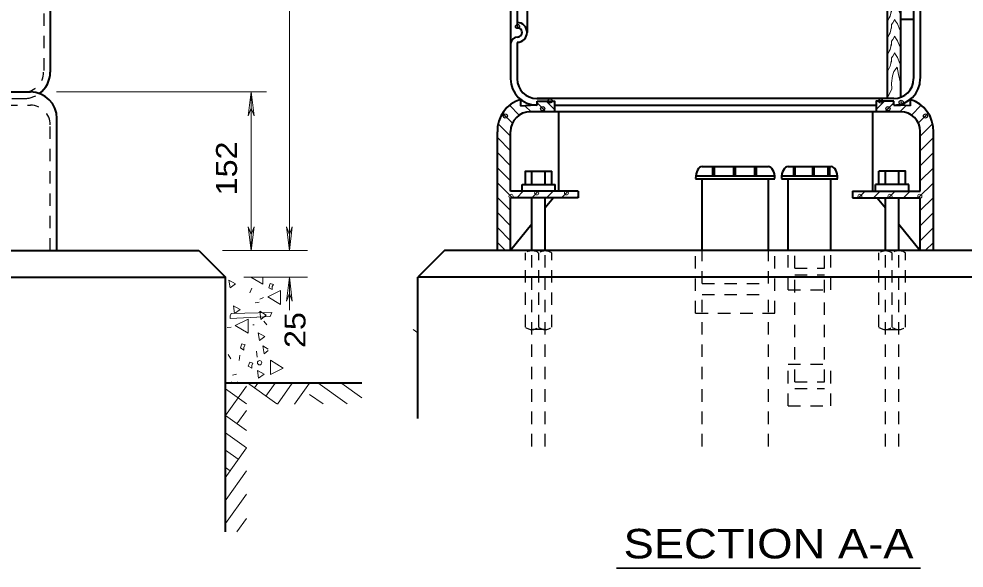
# Model space of a CAD drawing. Extents: x 312583 to 312854, y 144419 to 144597.
# Drawn here: x 312696.89 to 312731.16, y 144509.33 to 144529.22 of the extents above; entities that cross this region are included whole.
import ezdxf
from ezdxf.enums import TextEntityAlignment as Align

# ---------------------------------------------------------------- set-up
doc = ezdxf.new("R2010")
doc.units = 0
doc.header["$LTSCALE"] = 0.3
doc.header["$PDMODE"] = 32
doc.header["$PDSIZE"] = 0.15
doc.linetypes.add('SHORT_DASHED', pattern=[2.7, 1.5, -1.2])
doc.layers.add('1', color=7, linetype='Continuous', lineweight=25)
doc.layers.add('2', color=7, linetype='Continuous', lineweight=13)

msp = doc.modelspace()

# ---------------------------------------------------------------- linework, layer by layer
at = {"layer": '1', "lineweight": 40}
for p, q in [((312728.3725, 144566.588), (312728.3725, 144526.338)), ((312728.8555, 144566.542), (312728.8555, 144526.3763)), ((312698.0298, 144565.8673), (312698.0298, 144527.2963)), ((312729.3309, 144565.8673), (312729.3309, 144527.0586)), ((312729.5685, 144565.8673), (312729.5685, 144527.0586)), ((312715.3162, 144564.7863), (312715.3162, 144528.73)), ((312714.9559, 144564.6253), (312714.9559, 144528.8986)), ((312728.8555, 144529.213), (312729.3309, 144529.213)), ((312714.9559, 144528.3696), (312714.9559, 144527.0586)), ((312670.4758, 144526.5756), (312697.3091, 144526.5756)), ((312715.0785, 144526.3073), (312715.0785, 144526.0696)), ((312715.0785, 144526.0696), (312715.4389, 144526.1003)), ((312715.6765, 144526.1003), (312715.4389, 144526.1003)), ((312716.0982, 144526.338), (312715.6765, 144526.338)), ((312715.6765, 144526.338), (312716.0982, 144526.338)), ((312715.6765, 144526.1003), (312715.6765, 144526.246)), ((312715.6765, 144526.2076), (312715.6765, 144526.2306)), ((312728.6102, 144526.338), (312716.0982, 144526.338)), ((312716.3129, 144526.1003), (312716.3129, 144525.855)), ((312716.3129, 144526.1003), (312727.9739, 144526.1003)), ((312727.9739, 144526.1003), (312727.9739, 144525.855)), ((312728.6102, 144526.338), (312728.1962, 144526.338)), ((312728.6102, 144526.1003), (312728.6102, 144526.246)), ((312728.6102, 144526.2076), (312728.6102, 144526.2306)), ((312728.6102, 144526.1003), (312728.8555, 144526.1003)), ((312729.2082, 144526.0696), (312728.8555, 144526.1003)), ((312729.2082, 144526.3073), (312729.2082, 144526.0696)), ((312728.8555, 144525.855), (312715.4389, 144525.855)), ((312716.4509, 144525.855), (312716.4509, 144522.98)), ((312727.8359, 144525.855), (312727.8359, 144522.98)), ((312698.2675, 144520.8256), (312698.2675, 144525.6173)), ((312714.2429, 144520.818), (312714.2429, 144525.1343)), ((312714.7182, 144522.98), (312714.7182, 144525.142)), ((312729.5685, 144522.98), (312729.5685, 144525.142)), ((312730.0515, 144520.818), (312730.0515, 144525.1343)), ((312715.4925, 144523.2253), (312715.4925, 144523.7006)), ((312715.9755, 144523.2253), (312715.9755, 144523.7006)), ((312716.2132, 144523.2253), (312716.2132, 144523.7006)), ((312721.6642, 144523.8693), (312724.0639, 144523.8693)), ((312722.0552, 144523.532), (312722.0552, 144523.8693)), ((312722.1089, 144523.532), (312722.1089, 144523.8693)), ((312722.8065, 144523.532), (312722.8065, 144523.8693)), ((312722.8679, 144523.532), (312722.8679, 144523.8693)), ((312723.5732, 144523.532), (312723.5732, 144523.8693)), ((312723.6345, 144523.532), (312723.6345, 144523.8693)), ((312724.7769, 144523.8693), (312726.3332, 144523.8693)), ((312724.9915, 144523.532), (312724.9915, 144523.8693)), ((312725.0375, 144523.532), (312725.0375, 144523.8693)), ((312725.6815, 144523.532), (312725.6815, 144523.8693)), ((312725.7275, 144523.532), (312725.7275, 144523.8693)), ((312726.2335, 144523.532), (312726.2335, 144523.8693)), ((312726.2949, 144523.532), (312726.2949, 144523.8693)), ((312728.0735, 144523.2253), (312728.0735, 144523.7006)), ((312728.3112, 144523.2253), (312728.3112, 144523.7006)), ((312728.7942, 144523.2253), (312728.7942, 144523.7006)), ((312721.4265, 144523.4323), (312724.3015, 144523.4323)), ((312721.4342, 144523.532), (312724.2939, 144523.532)), ((312721.6642, 144520.8256), (312721.6642, 144523.4323)), ((312724.0639, 144520.8256), (312724.0639, 144523.4323)), ((312724.5392, 144523.4323), (312726.5785, 144523.4323)), ((312724.5469, 144523.532), (312726.5709, 144523.532)), ((312724.7769, 144520.8256), (312724.7769, 144523.4323)), ((312726.3332, 144520.8256), (312726.3332, 144523.4323)), ((312717.1715, 144522.98), (312714.7182, 144522.98)), ((312715.1399, 144523.2253), (312716.3359, 144523.2253)), ((312715.1399, 144522.98), (312715.1399, 144523.2253)), ((312716.3359, 144522.98), (312716.3359, 144523.2253)), ((312717.1715, 144522.98), (312717.1715, 144522.7423)), ((312727.1152, 144522.98), (312729.5685, 144522.98)), ((312727.1152, 144522.98), (312727.1152, 144522.7423)), ((312729.1545, 144523.2253), (312727.9509, 144523.2253)), ((312727.9509, 144522.98), (312727.9509, 144523.2253)), ((312729.1545, 144522.98), (312729.1545, 144523.2253)), ((312717.1715, 144522.7423), (312714.7182, 144522.7423)), ((312714.7182, 144520.8256), (312714.7182, 144522.7423)), ((312715.4925, 144520.8256), (312715.4925, 144522.7423)), ((312716.2745, 144522.7423), (312715.9755, 144522.3743)), ((312715.9755, 144520.8256), (312715.9755, 144522.7423)), ((312727.1152, 144522.7423), (312729.5685, 144522.7423)), ((312728.0122, 144522.7423), (312728.3112, 144522.3743)), ((312728.3112, 144520.8256), (312728.3112, 144522.7423)), ((312728.7942, 144520.8256), (312728.7942, 144522.7423)), ((312729.5685, 144520.8256), (312729.5685, 144522.7423)), ((312715.4925, 144521.784), (312714.7182, 144520.8256)), ((312728.7942, 144521.784), (312729.5685, 144520.8256)), ((312630.5861, 144520.8256), (312703.4195, 144520.8256)), ((312703.4195, 144520.8256), (312704.3778, 144519.8673)), ((312712.3185, 144520.8256), (312711.3602, 144519.8673)), ((312733.4019, 144520.8256), (312712.3185, 144520.8256)), ((312629.6278, 144519.8673), (312704.3778, 144519.8673)), ((312704.3778, 144510.6366), (312704.3778, 144519.8673)), ((312734.3602, 144519.8673), (312711.3602, 144519.8673)), ((312711.3602, 144514.746), (312711.3602, 144519.8673)), ((312704.3778, 144516.034), (312709.3249, 144516.034)), ((312704.6001, 144516.034), (312709.3249, 144516.034))]:
    msp.add_line(p, q, dxfattribs=at)
at = {"layer": '1', "linetype": 'SHORT_DASHED'}
for p, q in [((312697.7921, 144565.8673), (312697.7921, 144527.2963)), ((312670.7135, 144526.5756), (312697.0715, 144526.5756)), ((312670.4758, 144526.1003), (312697.3091, 144526.1003)), ((312670.7135, 144526.338), (312697.0715, 144526.338)), ((312698.0298, 144520.8256), (312698.0298, 144525.3796)), ((312715.2549, 144518.0503), (312715.2549, 144520.7413)), ((312715.4925, 144513.734), (312715.4925, 144520.8256)), ((312715.7379, 144518.0503), (312715.7379, 144520.7413)), ((312715.9755, 144513.734), (312715.9755, 144520.8256)), ((312716.2132, 144518.0503), (312716.2132, 144520.7413)), ((312721.4265, 144518.5563), (312721.4265, 144520.8256)), ((312721.6642, 144519.6373), (312721.6642, 144520.8256)), ((312724.0639, 144519.6373), (312724.0639, 144520.8256)), ((312724.3015, 144518.5563), (312724.3015, 144520.8256)), ((312724.7769, 144519.4073), (312724.7769, 144520.8256)), ((312725.0222, 144520.1893), (312725.0222, 144520.8256)), ((312726.0955, 144520.1893), (312726.0955, 144520.8256)), ((312726.3332, 144519.4073), (312726.3332, 144520.8256)), ((312728.0735, 144518.0503), (312728.0735, 144520.7413)), ((312728.3112, 144513.734), (312728.3112, 144520.8256)), ((312728.5489, 144518.0503), (312728.5489, 144520.7413)), ((312728.7942, 144513.734), (312728.7942, 144520.8256)), ((312729.0319, 144518.0503), (312729.0319, 144520.7413)), ((312725.0222, 144520.1893), (312726.0955, 144520.1893)), ((312725.0222, 144519.944), (312726.0955, 144519.944)), ((312725.0222, 144516.0723), (312725.0222, 144519.944)), ((312726.0955, 144516.0723), (312726.0955, 144519.944)), ((312721.6642, 144519.6373), (312724.0639, 144519.6373)), ((312721.6642, 144519.2386), (312724.0639, 144519.2386)), ((312721.6642, 144513.734), (312721.6642, 144519.2386)), ((312724.0639, 144513.734), (312724.0639, 144519.2386)), ((312724.7769, 144519.4073), (312726.3332, 144519.4073)), ((312721.4265, 144518.5563), (312724.3015, 144518.5563)), ((312715.9755, 144517.9736), (312715.4925, 144517.9736)), ((312728.3112, 144517.9736), (312728.7942, 144517.9736)), ((312724.7769, 144515.206), (312724.7769, 144516.7163)), ((312724.7769, 144516.7163), (312726.3332, 144516.7163)), ((312726.3332, 144515.206), (312726.3332, 144516.7163)), ((312725.0222, 144516.0723), (312726.0955, 144516.0723)), ((312725.0222, 144515.827), (312726.0955, 144515.827)), ((312724.7769, 144515.206), (312726.3332, 144515.206))]:
    msp.add_line(p, q, dxfattribs=at)
at = {"layer": '1', "lineweight": 13}
for p, q in [((312714.6799, 144526.0926), (312715.0325, 144525.7323)), ((312715.4619, 144525.855), (312715.2395, 144526.0773)), ((312715.9985, 144525.855), (312715.6765, 144526.1846)), ((312716.3205, 144525.9316), (312715.9985, 144526.2536)), ((312727.9662, 144525.9316), (312728.2882, 144526.2536)), ((312728.2882, 144525.855), (312728.6102, 144526.1846)), ((312728.8325, 144525.855), (312729.0472, 144526.0773)), ((312729.6069, 144526.0926), (312729.2542, 144525.7323)), ((312714.8025, 144525.4333), (312714.4269, 144525.809)), ((312714.4882, 144525.74), (312714.4805, 144525.7553)), ((312729.4842, 144525.4333), (312729.8599, 144525.809)), ((312729.7985, 144525.74), (312729.8139, 144525.7553)), ((312714.7182, 144524.9733), (312714.2812, 144525.4026)), ((312729.5685, 144524.9733), (312730.0055, 144525.4026))]:
    msp.add_line(p, q, dxfattribs=at)
at = {"layer": '1', "lineweight": 40}
for points in [[(312714.7182, 144565.8673), (312714.7182, 144528.2546), (312714.7182, 144527.0586)], [(312715.6765, 144526.246), (312716.3129, 144526.246), (312716.3129, 144525.8473)], [(312728.6102, 144526.246), (312727.9739, 144526.246), (312727.9739, 144525.8473)], [(312715.2549, 144523.2253), (312715.2549, 144523.7006), (312716.2132, 144523.7006)], [(312729.0319, 144523.2253), (312729.0319, 144523.7006), (312728.0735, 144523.7006)]]:
    msp.add_lwpolyline(points, dxfattribs=at)
for centre, radius, start, end in [((312714.9664, 144528.7319), 0.1681, 266.07729, 89.01788), ((312714.9559, 144528.7319), 0.3594, 270, 90), ((312714.9993, 144528.283), 0.2846, 98.90059, 186.11318), ((312697.0705, 144527.2944), 0.9583, 306.01567, 0), ((312715.6746, 144527.0548), 0.9583, 180, 270), ((312715.6746, 144527.0548), 0.7188, 180, 270), ((312728.6121, 144527.0548), 0.9583, 270, 0), ((312728.6121, 144527.0548), 0.7188, 270, 0), ((312697.3101, 144525.6173), 0.9583, 0, 90), ((312715.4332, 144525.1659), 1.1948, 107.31785, 181.66152), ((312728.8536, 144525.1659), 1.1948, 358.33848, 72.68215), ((312715.435, 144525.1381), 0.7188, 90, 180), ((312715.435, 144525.1381), 0.7188, 90, 180), ((312728.8517, 144525.1381), 0.7188, 0, 90), ((312728.8517, 144525.1381), 0.7188, 0, 90)]:
    msp.add_arc(centre, radius, start, end, dxfattribs=at)
at = {"layer": '1', "linetype": 'SHORT_DASHED'}
for centre, radius, start, end in [((312697.0705, 144527.2944), 0.7188, 270, 0), ((312697.0705, 144527.2944), 0.9583, 270, 306.01567), ((312697.3101, 144525.3777), 0.7188, 0, 90), ((312715.4954, 144520.4379), 0.3858, 51.61151, 128.38849), ((312715.9746, 144520.4045), 0.4125, 54.49327, 125.50673), ((312728.3122, 144520.4045), 0.4125, 54.49327, 125.50673), ((312728.7913, 144520.4379), 0.3858, 51.61151, 128.38849), ((312715.4954, 144518.3823), 0.4125, 234.49327, 305.50673), ((312715.9746, 144518.3823), 0.4125, 234.49327, 305.50673), ((312728.3122, 144518.3823), 0.4125, 234.49327, 305.50673), ((312728.7913, 144518.3823), 0.4125, 234.49327, 305.50673)]:
    msp.add_arc(centre, radius, start, end, dxfattribs=at)
at = {"layer": '1', "lineweight": 40}
for centre, major_axis, start_param, end_param in [((312721.6642, 144523.4352), (0, -0.4351), 3.1415927, 4.712389), ((312724.06, 144523.4352), (0, 0.4351), 4.712389, 6.2831853), ((312724.7788, 144523.4352), (0, -0.4351), 3.1415927, 4.712389), ((312726.3361, 144523.4352), (0, 0.4351), 4.712389, 6.2831853)]:
    msp.add_ellipse(centre, major_axis=major_axis, ratio=0.550661, start_param=start_param, end_param=end_param, dxfattribs=at)
at = {"layer": '1'}
for p in [(312714.9712, 144528.9446), (312716.1519, 144526.246), (312728.1349, 144526.246), (312728.8785, 144526.2), (312714.5265, 144525.7016), (312715.8835, 144525.97), (312728.4032, 144525.97), (312729.7602, 144525.7016)]:
    msp.add_point(p, dxfattribs=at)
at = {"layer": '2'}
for p, q in [((312706.6978, 144520.8256), (312706.6978, 144566.8256)), ((312698.2598, 144526.5756), (312705.8728, 144526.5756)), ((312705.3131, 144526.5756), (312705.2058, 144525.7093)), ((312705.3131, 144520.8256), (312705.3131, 144526.5756)), ((312705.3131, 144526.5756), (312705.4205, 144525.7093)), ((312705.2058, 144525.7093), (312705.3131, 144525.9853)), ((312705.4205, 144525.7093), (312705.3131, 144525.9853)), ((312714.7182, 144524.4366), (312714.2429, 144524.9196)), ((312729.5685, 144524.4366), (312730.0515, 144524.9196)), ((312714.7182, 144523.9), (312714.2429, 144524.3753)), ((312729.5685, 144523.9), (312730.0515, 144524.3753)), ((312714.7182, 144523.3556), (312714.2429, 144523.831)), ((312729.5685, 144523.3556), (312730.0515, 144523.831)), ((312714.7872, 144522.7423), (312714.2429, 144523.2866)), ((312714.9405, 144522.7423), (312715.1782, 144522.98)), ((312715.4849, 144522.7423), (312715.7225, 144522.98)), ((312716.0215, 144522.7423), (312716.2669, 144522.98)), ((312716.5659, 144522.7423), (312716.8035, 144522.98)), ((312727.3299, 144522.7423), (312727.5752, 144522.98)), ((312727.8742, 144522.7423), (312728.1119, 144522.98)), ((312728.4185, 144522.7423), (312728.6562, 144522.98)), ((312728.9629, 144522.7423), (312729.2005, 144522.98)), ((312729.4995, 144522.7423), (312730.0515, 144523.2866)), ((312714.7182, 144522.2746), (312714.2429, 144522.75)), ((312717.1102, 144522.7423), (312717.1715, 144522.8036)), ((312729.5685, 144522.2746), (312730.0515, 144522.75)), ((312714.7182, 144521.7303), (312714.2429, 144522.2056)), ((312729.5685, 144521.7303), (312730.0515, 144522.2056)), ((312705.2058, 144521.692), (312705.3131, 144521.416)), ((312705.3131, 144520.8256), (312705.2058, 144521.692)), ((312705.4205, 144521.692), (312705.3131, 144521.416)), ((312705.3131, 144520.8256), (312705.4205, 144521.692)), ((312706.5905, 144521.692), (312706.6978, 144521.416)), ((312706.6978, 144520.8256), (312706.5905, 144521.692)), ((312706.8051, 144521.692), (312706.6978, 144521.416)), ((312706.6978, 144520.8256), (312706.8051, 144521.692)), ((312714.7182, 144521.186), (312714.2429, 144521.6613)), ((312729.5685, 144521.186), (312730.0515, 144521.6613)), ((312714.5342, 144520.8256), (312714.2429, 144521.1246)), ((312729.7525, 144520.8256), (312730.0515, 144521.1246)), ((312704.2705, 144520.8256), (312707.3495, 144520.8256)), ((312705.0525, 144519.8673), (312707.3495, 144519.8673)), ((312705.3025, 144519.8673), (312705.7318, 144519.6066)), ((312705.7318, 144519.6066), (312705.7318, 144519.8673)), ((312706.6978, 144519.8673), (312706.5905, 144519.001)), ((312706.6978, 144518.671), (312706.6978, 144519.8673)), ((312706.6978, 144519.8673), (312706.8051, 144519.001)), ((312705.3361, 144519.461), (312705.2595, 144519.2923)), ((312706.5905, 144519.001), (312706.6978, 144519.277)), ((312706.8051, 144519.001), (312706.6978, 144519.277)), ((312705.4558, 144518.932), (312705.6015, 144518.9626)), ((312705.6245, 144519.0623), (312705.7548, 144519.1313)), ((312705.7734, 144518.2726), (312705.8807, 144518.1346)), ((312704.4391, 144518.0426), (312704.5925, 144518.0503)), ((312705.3786, 144518.1423), (312705.419, 144518.1331)), ((312711.3602, 144517.851), (312711.1915, 144517.966)), ((312705.5112, 144517.1854), (312705.5342, 144516.9708)), ((312704.4775, 144517.069), (312704.5695, 144516.9003)), ((312704.8769, 144516.8466), (312704.9076, 144517.0383)), ((312704.6405, 144516.3147), (312704.7862, 144516.353)), ((312705.1445, 144515.919), (312704.3778, 144514.8533)), ((312705.1445, 144515.275), (312704.3778, 144515.8193)), ((312704.6001, 144516.0723), (312704.5848, 144516.034)), ((312704.7151, 144516.034), (312704.7151, 144516.0416)), ((312704.8148, 144516.0723), (312704.7995, 144516.034)), ((312704.9298, 144516.034), (312704.9375, 144516.0416)), ((312706.2408, 144515.275), (312705.1751, 144516.034)), ((312705.5508, 144516.0263), (312705.4281, 144515.8576)), ((312706.1795, 144516.0263), (312705.8421, 144515.5586)), ((312706.8005, 144516.0263), (312706.2638, 144515.2596)), ((312707.4291, 144516.0263), (312706.8848, 144515.2596)), ((312708.7938, 144515.275), (312707.7281, 144516.034)), ((312709.3249, 144515.497), (312708.6021, 144516.011)), ((312707.9198, 144515.275), (312707.4291, 144515.62)), ((312704.3778, 144514.8533), (312705.1445, 144514.309)), ((312705.1445, 144515.0373), (312704.7918, 144514.5543)), ((312704.3778, 144514.2246), (312705.1445, 144513.6803)), ((312705.1445, 144513.6803), (312704.3701, 144512.5916)), ((312704.3778, 144513.596), (312704.8455, 144513.2663)), ((312704.3778, 144512.9673), (312704.5465, 144512.8446)), ((312705.1445, 144512.8446), (312704.4008, 144511.8096)), ((312705.1445, 144512.0013), (312704.3778, 144510.9356)), ((312705.1445, 144511.1273), (312704.7918, 144510.6366))]:
    msp.add_line(p, q, dxfattribs=at)
at = {"layer": '2', "lineweight": 35}
msp.add_line((312718.5579, 144509.3256), (312729.5801, 144509.3256), dxfattribs=at)
at = {"layer": '2'}
for points in [[(312728.3879, 144529.1286), (312728.4415, 144529.259), (312728.4799, 144529.3203), (312728.5029, 144529.4276), (312728.5105, 144529.5043), (312728.5335, 144529.466), (312728.5335, 144529.558), (312728.5335, 144529.6193), (312728.5795, 144529.6806), (312728.6332, 144529.788), (312728.6409, 144529.8033), (312728.6792, 144529.7496), (312728.7482, 144529.6423), (312728.8249, 144529.4276)], [(312728.3879, 144528.523), (312728.4415, 144528.6533), (312728.4799, 144528.7146), (312728.5029, 144528.822), (312728.5105, 144528.8986), (312728.5335, 144528.868), (312728.5335, 144528.9523), (312728.5335, 144529.0213), (312728.5795, 144529.0826), (312728.6332, 144529.19), (312728.6409, 144529.1976), (312728.6792, 144529.144), (312728.7482, 144529.0366), (312728.8249, 144528.822)], [(312728.3879, 144527.925), (312728.4415, 144528.0476), (312728.4799, 144528.109), (312728.5029, 144528.2163), (312728.5105, 144528.3006), (312728.5335, 144528.2623), (312728.5335, 144528.3543), (312728.5335, 144528.4156), (312728.5795, 144528.477), (312728.6332, 144528.5843), (312728.6409, 144528.592), (312728.6792, 144528.5383), (312728.7482, 144528.431), (312728.8249, 144528.2163)], [(312728.3879, 144527.3193), (312728.4415, 144527.442), (312728.4799, 144527.5033), (312728.5029, 144527.6106), (312728.5105, 144527.695), (312728.5335, 144527.6566), (312728.5335, 144527.7486), (312728.5335, 144527.81), (312728.5795, 144527.8713), (312728.6332, 144527.9786), (312728.6409, 144527.9863), (312728.6792, 144527.9326), (312728.7482, 144527.8253), (312728.8249, 144527.6106)], [(312728.3725, 144526.338), (312728.5412, 144526.683), (312728.5335, 144526.8976), (312728.5642, 144527.1583), (312728.6179, 144527.3193), (312728.7329, 144527.4726), (312728.7789, 144527.212), (312728.8402, 144526.936)], [(312705.9336, 144517.2586), (312705.7322, 144517.3756), (312705.7782, 144517.092), (312705.9336, 144517.2101)]]:
    msp.add_lwpolyline(points, dxfattribs=at)
for points in [[(312704.5541, 144519.4763), (312704.7458, 144519.622), (312704.5081, 144519.76)], [(312706.0736, 144519.5223), (312706.1273, 144519.599), (312706.0046, 144519.6373), (312705.9509, 144519.484), (312706.0736, 144519.415)], [(312706.3788, 144518.8706), (312706.3788, 144519.3843), (312705.9111, 144519.1543)], [(312704.5471, 144518.4673), (312704.5931, 144518.5516), (312706.0604, 144518.5899), (312706.0068, 144518.4366), (312704.5471, 144518.3676)], [(312704.7095, 144518.5439), (312704.9088, 144518.6896), (312704.6711, 144518.8276)], [(312705.6614, 144518.3367), (312705.853, 144518.49), (312705.623, 144518.628)], [(312705.202, 144517.8356), (312705.202, 144518.3493), (312704.7343, 144518.1193)], [(312705.6132, 144517.5688), (312705.8048, 144517.7145), (312705.5672, 144517.8525)], [(312705.0448, 144517.3296), (312705.0985, 144517.414), (312704.9758, 144517.4446), (312704.9221, 144517.299), (312705.0448, 144517.2223)], [(312706.0097, 144516.8543), (312706.0097, 144516.333), (312706.4773, 144516.5706)], [(312705.332, 144516.6704), (312705.378, 144516.7547), (312705.263, 144516.7854), (312705.2094, 144516.6397), (312705.332, 144516.563)], [(312705.5793, 144516.2026), (312705.7787, 144516.3483), (312705.541, 144516.4863)]]:
    msp.add_lwpolyline(points, close=True, dxfattribs=at)
msp.add_circle((312705.6164, 144516.7647), 0.0784, dxfattribs=at)
for p in [(312715.6612, 144522.9186), (312716.7422, 144522.9186), (312714.7335, 144522.796), (312727.3835, 144522.796), (312728.4722, 144522.796), (312729.5532, 144522.796)]:
    msp.add_point(p, dxfattribs=at)

# ---------------------------------------------------------------- texts
at = {"layer": '2', "width": 1.15}
for s, p in [('152 ', (312704.7982, 144522.8297)), ('25 ', (312707.2812, 144517.2979))]:
    msp.add_text(s, height=0.76, rotation=90, dxfattribs=at).set_placement(p)
msp.add_text('SECTION A-A', height=1.07, dxfattribs=at).set_placement((312724.0705, 144509.6754), align=Align.CENTER)

doc.saveas('drawing.dxf')
